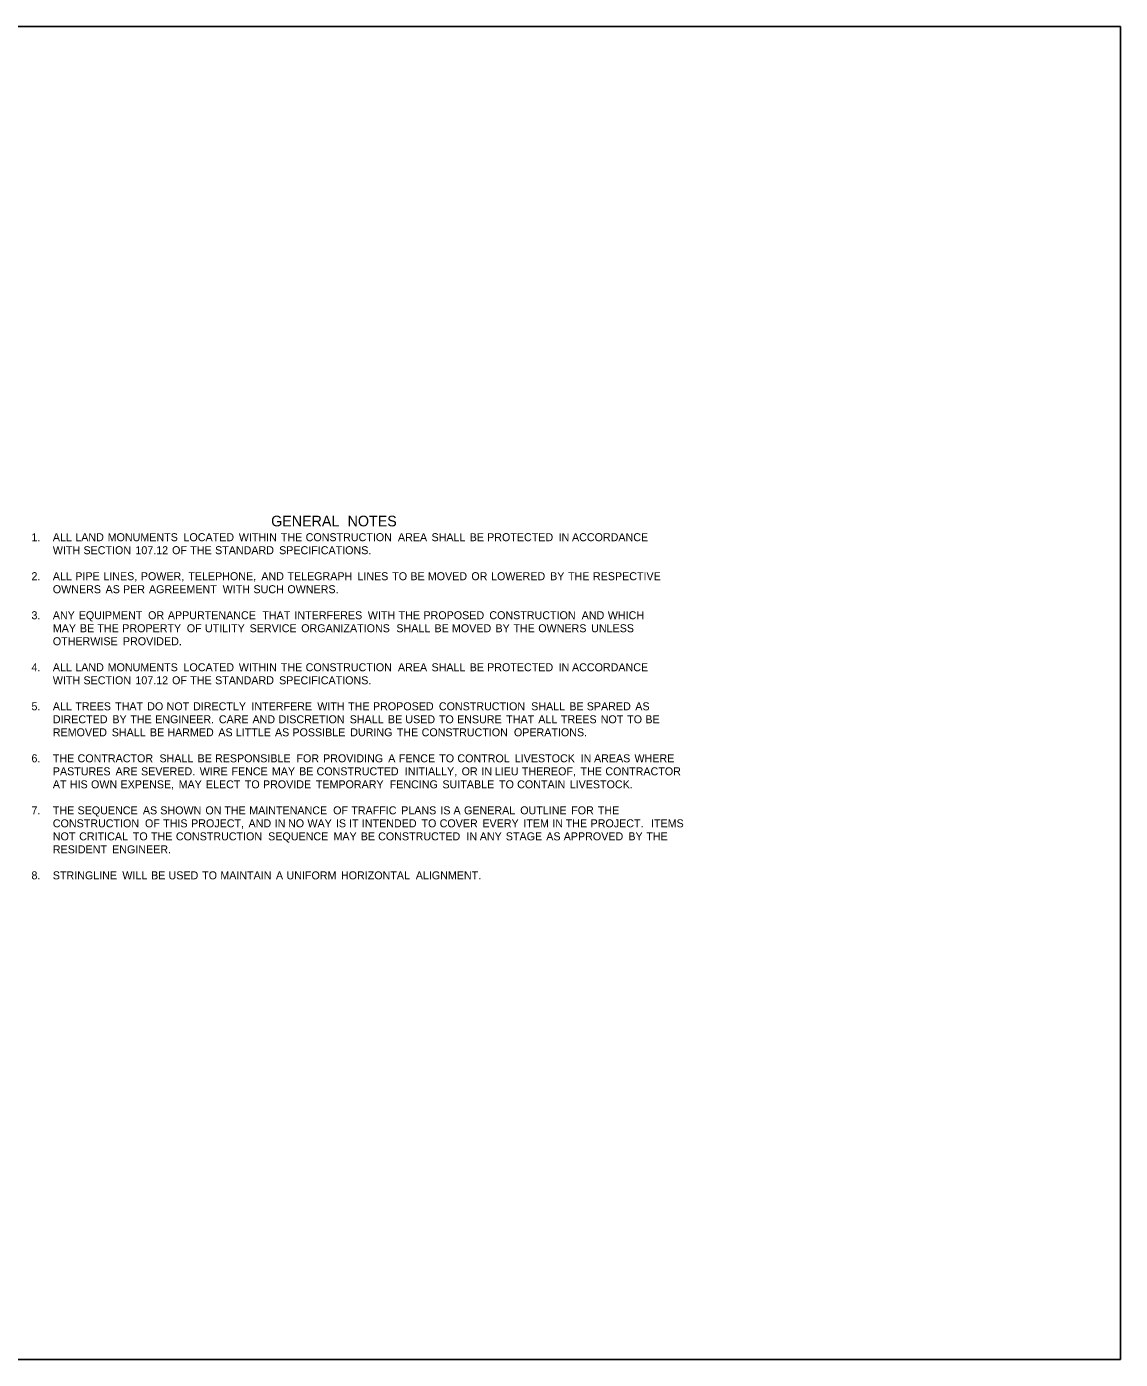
# Model space of a CAD drawing. Extents: x 2262258 to 2263883, y -3124557 to -3123558.
# Drawn here: x 2263063 to 2263883, y -3124557 to -3123558 of the extents above; entities that cross this region are included whole.
import ezdxf

# ---------------------------------------------------------------- set-up
doc = ezdxf.new("R2010")
doc.units = 0
doc.layers.add('Default', color=7, linetype='Continuous')
doc.layers.add('DSN_DRFT_Named-Boundary', color=7, linetype='Continuous')

msp = doc.modelspace()

# ---------------------------------------------------------------- linework, layer by layer
at = {"layer": 'DSN_DRFT_Named-Boundary'}
msp.add_lwpolyline([(2262257.96, -3124557.39), (2263882.96, -3124557.39), (2263882.96, -3123558.34), (2262257.96, -3123558.34)], close=True, dxfattribs=at)

# ---------------------------------------------------------------- texts
at = {"layer": 'Default'}
for s, height, p in [('GENERAL', 8, (2263246.48, -3123932.95)), (' NOTES', 8, (2263300.81, -3123932.95)), ('1.', 6, (2263066.84, -3123944.08)), ('ALL', 6, (2263082.85, -3123944.08)), (' LAND', 6, (2263097.46, -3123944.08)), (' MONUMENTS', 6, (2263121.71, -3123944.08)), (' LOCATED', 6, (2263178.56, -3123944.08)), (' WITHIN', 6, (2263220.03, -3123944.08)), (' THE', 6, (2263251.48, -3123944.08)), (' CONSTRUCTION', 6, (2263270.12, -3123944.08)), (' AREA', 6, (2263339.3, -3123944.08)), (' SHALL', 6, (2263364.48, -3123944.08)), (' BE', 6, (2263393.07, -3123944.08)), (' PROTECTED', 6, (2263406.14, -3123944.08)), (' IN', 6, (2263459.72, -3123944.08)), (' ACCORDANCE', 6, (2263469.75, -3123944.08)), ('WITH', 6, (2263082.85, -3123953.83)), (' SECTION', 6, (2263103.59, -3123953.83)), (' 107.12', 6, (2263142.5, -3123953.83)), (' OF', 6, (2263170.01, -3123953.83)), (' THE', 6, (2263183.6, -3123953.83)), (' STANDARD', 6, (2263202.24, -3123953.83)), (' SPECIFICATIONS.', 6, (2263250.24, -3123953.83)), ('2.', 6, (2263066.84, -3123973.33)), ('ALL', 6, (2263082.85, -3123973.33)), (' PIPE', 6, (2263097.46, -3123973.33)), (' LINES,', 6, (2263118.45, -3123973.33)), (' POWER,', 6, (2263146.59, -3123973.33)), (' TELEPHONE,', 6, (2263182.17, -3123973.33)), (' AND', 6, (2263236.87, -3123973.33)), (' TELEGRAPH', 6, (2263256.45, -3123973.33)), (' LINES', 6, (2263308.89, -3123973.33)), (' TO', 6, (2263335, -3123973.33)), (' BE', 6, (2263348.6, -3123973.33)), (' MOVED', 6, (2263361.67, -3123973.33)), (' OR', 6, (2263394.29, -3123973.33)), (' LOWERED', 6, (2263409.08, -3123973.33)), (' BY', 6, (2263453.35, -3123973.33)), (' THE', 6, (2263466.8, -3123973.33)), (' RESPECTIVE', 6, (2263485.45, -3123973.33)), ('OWNERS', 6, (2263082.85, -3123983.08)), (' AS', 6, (2263120.14, -3123983.08)), (' PER', 6, (2263133.21, -3123983.08)), (' AGREEMENT', 6, (2263152.67, -3123983.08)), (' WITH', 6, (2263207.93, -3123983.08)), (' SUCH', 6, (2263231, -3123983.08)), (' OWNERS.', 6, (2263256.41, -3123983.08)), ('3.', 6, (2263066.84, -3124002.58)), ('ANY', 6, (2263082.85, -3124002.58)), (' EQUIPMENT', 6, (2263100.03, -3124002.58)), (' OR', 6, (2263152.03, -3124002.58)), (' APPURTENANCE', 6, (2263166.82, -3124002.58)), (' THAT', 6, (2263237.65, -3124002.58)), (' INTERFERES', 6, (2263261.7, -3124002.58)), (' WITH', 6, (2263316.7, -3124002.58)), (' THE', 6, (2263339.76, -3124002.58)), (' PROPOSED', 6, (2263358.41, -3124002.58)), (' CONSTRUCTION', 6, (2263407.82, -3124002.58)), (' AND', 6, (2263477, -3124002.58)), (' WHICH', 6, (2263496.58, -3124002.58)), ('MAY', 6, (2263082.85, -3124012.33)), (' BE', 6, (2263100.95, -3124012.33)), (' THE', 6, (2263114.02, -3124012.33)), (' PROPERTY', 6, (2263132.67, -3124012.33)), (' OF', 6, (2263181.06, -3124012.33)), (' UTILITY', 6, (2263194.64, -3124012.33)), (' SERVICE', 6, (2263228.12, -3124012.33)), (' ORGANIZATIONS', 6, (2263266.8, -3124012.33)), (' SHALL', 6, (2263338.1, -3124012.33)), (' BE', 6, (2263366.69, -3124012.33)), (' MOVED', 6, (2263379.76, -3124012.33)), (' BY', 6, (2263412.38, -3124012.33)), (' THE', 6, (2263425.83, -3124012.33)), (' OWNERS', 6, (2263444.48, -3124012.33)), (' UNLESS', 6, (2263484.1, -3124012.33)), ('OTHERWISE', 6, (2263082.85, -3124022.08)), (' PROVIDED.', 6, (2263133.17, -3124022.08)), ('4.', 6, (2263066.84, -3124041.58)), ('ALL', 6, (2263082.85, -3124041.58)), (' LAND', 6, (2263097.46, -3124041.58)), (' MONUMENTS', 6, (2263121.71, -3124041.58)), (' LOCATED', 6, (2263178.56, -3124041.58)), (' WITHIN', 6, (2263220.03, -3124041.58)), (' THE', 6, (2263251.48, -3124041.58)), (' CONSTRUCTION', 6, (2263270.12, -3124041.58)), (' AREA', 6, (2263339.3, -3124041.58)), (' SHALL', 6, (2263364.48, -3124041.58)), (' BE', 6, (2263393.07, -3124041.58)), (' PROTECTED', 6, (2263406.14, -3124041.58)), (' IN', 6, (2263459.72, -3124041.58)), (' ACCORDANCE', 6, (2263469.75, -3124041.58)), ('WITH', 6, (2263082.85, -3124051.33)), (' SECTION', 6, (2263103.59, -3124051.33)), (' 107.12', 6, (2263142.5, -3124051.33)), (' OF', 6, (2263170.01, -3124051.33)), (' THE', 6, (2263183.6, -3124051.33)), (' STANDARD', 6, (2263202.24, -3124051.33)), (' SPECIFICATIONS.', 6, (2263250.24, -3124051.33)), ('5.', 6, (2263066.84, -3124070.83)), ('ALL', 6, (2263082.85, -3124070.83)), (' TREES', 6, (2263097.46, -3124070.83)), (' THAT', 6, (2263127.31, -3124070.83)), (' DO', 6, (2263151.36, -3124070.83)), (' NOT', 6, (2263165.89, -3124070.83)), (' DIRECTLY', 6, (2263185.74, -3124070.83)), (' INTERFERE', 6, (2263229.47, -3124070.83)), (' WITH', 6, (2263278.86, -3124070.83)), (' THE', 6, (2263301.93, -3124070.83)), (' PROPOSED', 6, (2263320.58, -3124070.83)), (' CONSTRUCTION', 6, (2263369.98, -3124070.83)), (' SHALL', 6, (2263439.16, -3124070.83)), (' BE', 6, (2263467.75, -3124070.83)), (' SPARED', 6, (2263480.82, -3124070.83)), (' AS', 6, (2263517.18, -3124070.83)), ('DIRECTED', 6, (2263082.85, -3124080.58)), (' BY', 6, (2263125.26, -3124080.58)), (' THE', 6, (2263138.71, -3124080.58)), (' ENGINEER.', 6, (2263157.35, -3124080.58)), (' CARE', 6, (2263205.07, -3124080.58)), (' AND', 6, (2263230.25, -3124080.58)), (' DISCRETION', 6, (2263249.83, -3124080.58)), (' SHALL', 6, (2263303.17, -3124080.58)), (' BE', 6, (2263331.77, -3124080.58)), (' USED', 6, (2263344.83, -3124080.58)), (' TO', 6, (2263370.01, -3124080.58)), (' ENSURE', 6, (2263383.6, -3124080.58)), (' THAT', 6, (2263420.43, -3124080.58)), (' ALL', 6, (2263444.48, -3124080.58)), (' TREES', 6, (2263461.42, -3124080.58)), (' NOT', 6, (2263491.26, -3124080.58)), (' TO', 6, (2263511.12, -3124080.58)), (' BE', 6, (2263524.72, -3124080.58)), ('REMOVED', 6, (2263082.85, -3124090.33)), (' SHALL', 6, (2263124.79, -3124090.33)), (' BE', 6, (2263153.39, -3124090.33)), (' HARMED', 6, (2263166.45, -3124090.33)), (' AS', 6, (2263204.66, -3124090.33)), (' LITTLE', 6, (2263217.74, -3124090.33)), (' AS', 6, (2263247.1, -3124090.33)), (' POSSIBLE', 6, (2263260.18, -3124090.33)), (' DURING', 6, (2263303.53, -3124090.33)), (' THE', 6, (2263338.4, -3124090.33)), (' CONSTRUCTION', 6, (2263357.05, -3124090.33)), (' OPERATIONS.', 6, (2263426.23, -3124090.33)), ('6.', 6, (2263066.84, -3124109.83)), ('THE', 6, (2263082.85, -3124109.83)), (' CONTRACTOR', 6, (2263099.17, -3124109.83)), (' SHALL', 6, (2263160.54, -3124109.83)), (' BE', 6, (2263189.13, -3124109.83)), (' RESPONSIBLE', 6, (2263202.19, -3124109.83)), (' FOR', 6, (2263263.25, -3124109.83)), (' PROVIDING', 6, (2263283.16, -3124109.83)), (' A', 6, (2263332.01, -3124109.83)), (' FENCE', 6, (2263339.95, -3124109.83)), (' TO', 6, (2263370.24, -3124109.83)), (' CONTROL', 6, (2263383.84, -3124109.83)), (' LIVESTOCK', 6, (2263426.86, -3124109.83)), (' IN', 6, (2263476.23, -3124109.83)), (' AREAS', 6, (2263486.25, -3124109.83)), (' WHERE', 6, (2263516.57, -3124109.83)), ('PASTURES', 6, (2263082.85, -3124119.58)), (' ARE', 6, (2263127.61, -3124119.58)), (' SEVERED.', 6, (2263146.73, -3124119.58)), (' WIRE', 6, (2263190.73, -3124119.58)), (' FENCE', 6, (2263214.49, -3124119.58)), (' MAY', 6, (2263244.79, -3124119.58)), (' BE', 6, (2263265.22, -3124119.58)), (' CONSTRUCTED', 6, (2263278.29, -3124119.58)), (' INITIALLY,', 6, (2263344.45, -3124119.58)), (' OR', 6, (2263387.02, -3124119.58)), (' IN', 6, (2263401.81, -3124119.58)), (' LIEU', 6, (2263411.84, -3124119.58)), (' THEREOF,', 6, (2263432.12, -3124119.58)), (' THE', 6, (2263476.1, -3124119.58)), (' CONTRACTOR', 6, (2263494.74, -3124119.58)), ('AT', 6, (2263082.85, -3124129.33)), (' HIS', 6, (2263093.39, -3124129.33)), (' OWN', 6, (2263109.26, -3124129.33)), (' EXPENSE,', 6, (2263131.39, -3124129.33)), (' MAY', 6, (2263174.91, -3124129.33)), (' ELECT', 6, (2263195.34, -3124129.33)), (' TO', 6, (2263224.53, -3124129.33)), (' PROVIDE', 6, (2263238.12, -3124129.33)), (' TEMPORARY', 6, (2263277.74, -3124129.33)), (' FENCING', 6, (2263333.11, -3124129.33)), (' SUITABLE', 6, (2263372.64, -3124129.33)), (' TO', 6, (2263415.06, -3124129.33)), (' CONTAIN', 6, (2263428.65, -3124129.33)), (' LIVESTOCK.', 6, (2263468.02, -3124129.33)), ('7.', 6, (2263066.84, -3124148.83)), ('THE', 6, (2263082.85, -3124148.83)), (' SEQUENCE', 6, (2263099.17, -3124148.83)), (' AS', 6, (2263148.11, -3124148.83)), (' SHOWN', 6, (2263161.18, -3124148.83)), (' ON', 6, (2263194.96, -3124148.83)), (' THE', 6, (2263209.18, -3124148.83)), (' MAINTENANCE', 6, (2263227.83, -3124148.83)), (' OF', 6, (2263290.73, -3124148.83)), (' TRAFFIC', 6, (2263304.32, -3124148.83)), (' PLANS', 6, (2263341.71, -3124148.83)), (' IS', 6, (2263371.09, -3124148.83)), (' A', 6, (2263380.9, -3124148.83)), (' GENERAL', 6, (2263388.83, -3124148.83)), (' OUTLINE', 6, (2263430.94, -3124148.83)), (' FOR', 6, (2263469.15, -3124148.83)), (' THE', 6, (2263489.06, -3124148.83)), ('CONSTRUCTION', 6, (2263082.85, -3124158.58)), (' OF', 6, (2263149.7, -3124158.58)), (' THIS', 6, (2263163.29, -3124158.58)), (' PROJECT,', 6, (2263184.27, -3124158.58)), (' AND', 6, (2263227.31, -3124158.58)), (' IN', 6, (2263246.9, -3124158.58)), (' NO', 6, (2263256.92, -3124158.58)), (' WAY', 6, (2263271.45, -3124158.58)), (' IS', 6, (2263292.81, -3124158.58)), (' IT', 6, (2263302.62, -3124158.58)), (' INTENDED', 6, (2263312.23, -3124158.58)), (' TO', 6, (2263356.96, -3124158.58)), (' COVER', 6, (2263370.56, -3124158.58)), (' EVERY', 6, (2263402.59, -3124158.58)), (' ITEM', 6, (2263433.28, -3124158.58)), (' IN', 6, (2263455, -3124158.58)), (' THE', 6, (2263465.03, -3124158.58)), (' PROJECT.', 6, (2263483.68, -3124158.58)), ('  ITEMS', 6, (2263526.73, -3124158.58)), ('NOT', 6, (2263082.85, -3124168.33)), (' CRITICAL', 6, (2263100.38, -3124168.33)), (' TO', 6, (2263140.6, -3124168.33)), (' THE', 6, (2263154.2, -3124168.33)), (' CONSTRUCTION', 6, (2263172.85, -3124168.33)), (' SEQUENCE', 6, (2263242.03, -3124168.33)), (' MAY', 6, (2263290.96, -3124168.33)), (' BE', 6, (2263311.4, -3124168.33)), (' CONSTRUCTED', 6, (2263324.46, -3124168.33)), (' IN', 6, (2263390.62, -3124168.33)), (' ANY', 6, (2263400.65, -3124168.33)), (' STAGE', 6, (2263420.15, -3124168.33)), (' AS', 6, (2263450.45, -3124168.33)), (' APPROVED', 6, (2263463.53, -3124168.33)), (' BY', 6, (2263512, -3124168.33)), (' THE', 6, (2263525.45, -3124168.33)), ('RESIDENT', 6, (2263082.85, -3124178.08)), (' ENGINEER.', 6, (2263125.07, -3124178.08)), ('8.', 6, (2263066.84, -3124197.58)), ('STRINGLINE', 6, (2263082.85, -3124197.58)), (' WILL', 6, (2263132.71, -3124197.58)), (' BE', 6, (2263154.3, -3124197.58)), (' USED', 6, (2263167.37, -3124197.58)), (' TO', 6, (2263192.54, -3124197.58)), (' MAINTAIN', 6, (2263206.14, -3124197.58)), (' A', 6, (2263247.83, -3124197.58)), (' UNIFORM', 6, (2263255.77, -3124197.58)), (' HORIZONTAL', 6, (2263296.58, -3124197.58)), (' ALIGNMENT.', 6, (2263352.65, -3124197.58))]:
    msp.add_text(s, height=height, dxfattribs=at).set_placement(p)

doc.saveas('drawing.dxf')
